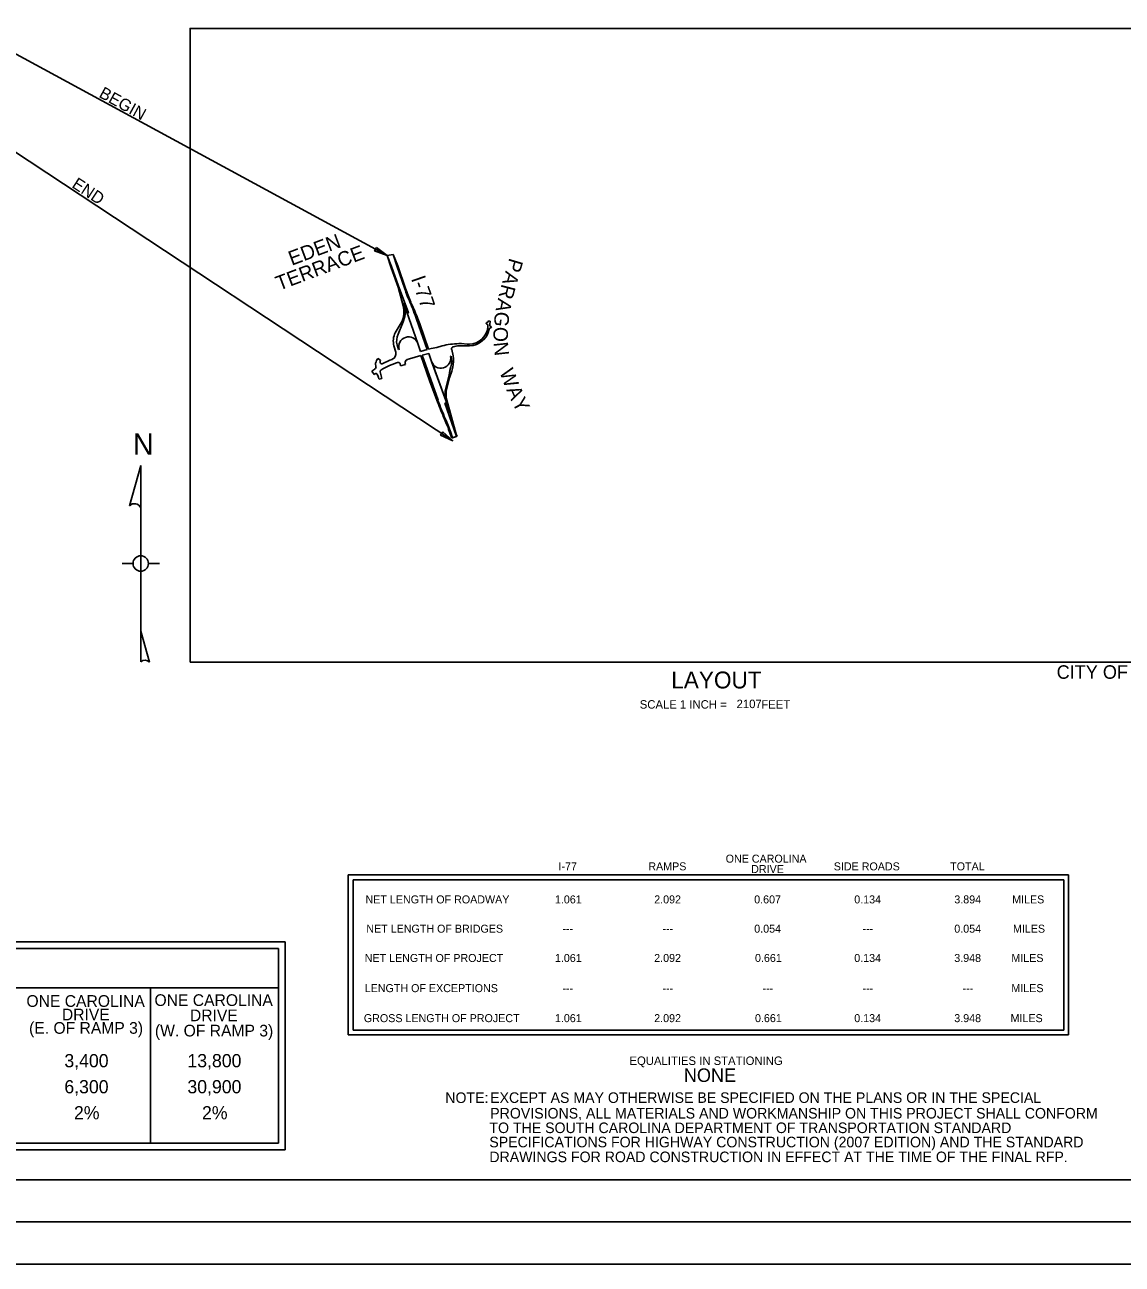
# Model space of a CAD drawing. Extents: x 1524103 to 2096450, y 1024229 to 1162569.
# Drawn here: x 2037540 to 2064966, y 1113991 to 1144974 of the extents above; entities that cross this region are included whole.
import ezdxf

# ---------------------------------------------------------------- set-up
doc = ezdxf.new("R2010")
doc.units = 0
for name, color, linetype in [('Default', 7, 'Continuous'), ('GN_TitleSheetMap', 7, 'Continuous'), ('RD_PD_EOP', 7, 'Continuous'), ('RD_SHT_Bndy', 7, 'Continuous'), ('RD_SHT_IplotShp', 7, 'Continuous'), ('RD_SHT_TX', 7, 'Continuous'), ('RD_TX_TitleSht', 7, 'Continuous')]:
    doc.layers.add(name, color=color, linetype=linetype)

msp = doc.modelspace()

# ---------------------------------------------------------------- linework, layer by layer
at = {"layer": 'GN_TitleSheetMap'}
msp.add_lwpolyline([(2041670, 1129041), (2068070, 1129041), (2068070, 1144881), (2041670, 1144881)], close=True, dxfattribs=at)
at = {"layer": 'RD_PD_EOP'}
for p, q in [((2046595, 1139210), (2046749, 1139230)), ((2046749, 1139230), (2046595, 1139210)), ((2046595, 1139210), (2046684, 1138923)), ((2046861, 1138951), (2046749, 1139230)), ((2046749, 1139230), (2046838, 1138948)), ((2046838, 1138948), (2046749, 1139230)), ((2046838, 1138948), (2047035, 1138376)), ((2047035, 1138376), (2046838, 1138948)), ((2047056, 1138383), (2046861, 1138951)), ((2046684, 1138923), (2046693, 1138897)), ((2046693, 1138897), (2046870, 1138411)), ((2046714, 1138904), (2046709, 1138917)), ((2046709, 1138917), (2046714, 1138904)), ((2046875, 1138461), (2046714, 1138904)), ((2046714, 1138904), (2046875, 1138461)), ((2046870, 1138411), (2046994, 1137948)), ((2047127, 1137771), (2046875, 1138461)), ((2046875, 1138461), (2047127, 1137771)), ((2047011, 1138018), (2047016, 1138020)), ((2047016, 1138020), (2047011, 1138018)), ((2047027, 1137957), (2047011, 1138018)), ((2047011, 1138018), (2047027, 1137957)), ((2047016, 1138020), (2047117, 1137767)), ((2047117, 1137767), (2047016, 1138020)), ((2047027, 1137957), (2047363, 1137008)), ((2047027, 1137957), (2047363, 1137009)), ((2047117, 1137767), (2047127, 1137771)), ((2047127, 1137771), (2047117, 1137767)), ((2046946, 1137523), (2046797, 1137275)), ((2046871, 1137239), (2046976, 1137508)), ((2046955, 1137541), (2046946, 1137523)), ((2046976, 1137508), (2046985, 1137526)), ((2047333, 1137611), (2047600, 1136856)), ((2047600, 1136856), (2047333, 1137611)), ((2047409, 1137497), (2047362, 1137622)), ((2047632, 1136865), (2047409, 1137497)), ((2049076, 1137532), (2049070, 1137501)), ((2049114, 1137447), (2049110, 1137408)), ((2049168, 1137561), (2049128, 1137573)), ((2049160, 1137480), (2049168, 1137561)), ((2049198, 1137403), (2049205, 1137426)), ((2046766, 1136949), (2046810, 1136789)), ((2046877, 1136856), (2046845, 1136970)), ((2046894, 1136861), (2046877, 1136856)), ((2047433, 1136810), (2047363, 1137008)), ((2047363, 1137008), (2047433, 1136810)), ((2047600, 1136856), (2047433, 1136810)), ((2047433, 1136810), (2047600, 1136856)), ((2047468, 1136713), (2047634, 1136759)), ((2047634, 1136759), (2047468, 1136713)), ((2047692, 1136882), (2047632, 1136865)), ((2047634, 1136759), (2047706, 1136554)), ((2047706, 1136554), (2047634, 1136759)), ((2047834, 1136908), (2047692, 1136882)), ((2047969, 1136945), (2047834, 1136908)), ((2048210, 1136857), (2048206, 1136856)), ((2048243, 1136696), (2048210, 1136857)), ((2048450, 1137004), (2048388, 1137003)), ((2048422, 1136948), (2048656, 1136951)), ((2048594, 1136993), (2048450, 1137004)), ((2048652, 1136993), (2048594, 1136993)), ((2046365, 1136635), (2046333, 1136584)), ((2046433, 1136594), (2046365, 1136635)), ((2046722, 1136615), (2046723, 1136611)), ((2046920, 1136498), (2046933, 1136450)), ((2046933, 1136450), (2047054, 1136483)), ((2047054, 1136483), (2047047, 1136507)), ((2047100, 1136608), (2047154, 1136627)), ((2047154, 1136627), (2047435, 1136704)), ((2047435, 1136704), (2047665, 1136054)), ((2047867, 1135586), (2047468, 1136713)), ((2047468, 1136713), (2047867, 1135586)), ((2048065, 1135580), (2047706, 1136554)), ((2048065, 1135580), (2047709, 1136548)), ((2048180, 1136683), (2048197, 1136687)), ((2046261, 1136350), (2046216, 1136318)), ((2046216, 1136318), (2046275, 1136234)), ((2046275, 1136234), (2046293, 1136246)), ((2046311, 1136444), (2046317, 1136419)), ((2046460, 1136130), (2046419, 1136300)), ((2048144, 1136212), (2048062, 1135893)), ((2048087, 1135886), (2048154, 1136147)), ((2048166, 1136330), (2048144, 1136212)), ((2048154, 1136147), (2048210, 1136319)), ((2048191, 1136427), (2048166, 1136330)), ((2048210, 1136319), (2048235, 1136416)), ((2046393, 1136125), (2046395, 1136114)), ((2046395, 1136114), (2046460, 1136130)), ((2047665, 1136054), (2047858, 1135545)), ((2048050, 1135516), (2048041, 1135513)), ((2048041, 1135513), (2048050, 1135516)), ((2048141, 1135282), (2048050, 1135516)), ((2048050, 1135516), (2048141, 1135282)), ((2048065, 1135580), (2048147, 1135284)), ((2048147, 1135284), (2048065, 1135580)), ((2048324, 1134743), (2048090, 1135587)), ((2048041, 1135513), (2048333, 1134686)), ((2048333, 1134686), (2048041, 1135513)), ((2048147, 1135284), (2048141, 1135282)), ((2048141, 1135282), (2048147, 1135284)), ((2048164, 1134775), (2048206, 1134656)), ((2048227, 1134652), (2048185, 1134783)), ((2048185, 1134783), (2048227, 1134652)), ((2048206, 1134656), (2048210, 1134647)), ((2048210, 1134647), (2048227, 1134652)), ((2048338, 1134688), (2048227, 1134652)), ((2048227, 1134652), (2048333, 1134686)), ((2048343, 1134689), (2048324, 1134743)), ((2048333, 1134686), (2048343, 1134689))]:
    msp.add_line(p, q, dxfattribs=at)
for points in [[(2046709, 1138917), (2046709, 1138917), (2046704, 1138929), (2046595, 1139210)], [(2046595, 1139210), (2046704, 1138929), (2046709, 1138917)], [(2047206, 1137998), (2047206, 1137998)]]:
    msp.add_lwpolyline(points, dxfattribs=at)
for centre, radius, start, end in [((2051713, 1139983), 4946, 198.9531, 203.2944), ((2051713, 1139983), 4946, 198.9531, 203.2944), ((2051713, 1139983), 4924, 198.9531, 203.2944), ((2041007, 1135373), 6710, 19.482, 23.2944), ((2041007, 1135373), 6710, 19.482, 23.2944), ((2041007, 1135373), 6732, 22.9513, 23.2944), ((2041064, 1135235), 6735, 20.7529, 24.2229), ((2041064, 1135235), 6735, 24.2229, 24.2235), ((2046433, 1137797), 581, 333.8563, 15.0109), ((2046433, 1137797), 615, 333.8563, 15.0109), ((2048648, 1137457), 464, 270.3929, 353.919), ((2049066, 1137453), 48.5, 353.919, 84.6269), ((2049080, 1137580), 48.5, 265.1461, 351.7715), ((2049193, 1137354), 48.5, 84.9978, 169.3164), ((2049208, 1137475), 48.5, 173.919, 266.9772), ((2047212, 1137071), 462, 153.8253, 195.3889), ((2047212, 1137071), 380, 153.8313, 195.3889), ((2047131, 1136926), 246, 19.482, 195.3889), ((2048648, 1137457), 506, 270.8238, 349.3164), ((2046672, 1136750), 144, 290.327, 15.3889), ((2047131, 1136926), 246, 19.482, 19.5594), ((2048399, 1135384), 1619, 90.3929, 105.3889), ((2048263, 1136868), 58.5, 106.1784, 191.3824), ((2048414, 1136349), 599, 91.819, 106.1784), ((2048445, 1135368), 1581, 90.8238, 91.819), ((2046489, 1136488), 183, 148.2706, 193.6417), ((2046457, 1136534), 38.5, 169.918, 297.8932), ((2046762, 1136480), 349, 160.9551, 169.918), ((2047439, 1134678), 1942, 107.393, 121.072), ((2047439, 1134678), 2061, 110.327, 117.8932), ((2046873, 1136485), 48.5, 15.3889, 107.393), ((2047128, 1136529), 83.5, 109.3689, 195.3889), ((2047938, 1136636), 246, 199.482, 10.9973), ((2047938, 1136636), 246, 199.482, 200.9312), ((2047626, 1136572), 583, 345.6281, 11.3824), ((2047626, 1136572), 629, 345.6281, 11.3824), ((2047439, 1134678), 2046, 123.8046, 125.1779), ((2046315, 1136215), 38.5, 30.7084, 125.1779), ((2046280, 1136410), 38.5, 303.8046, 13.6417), ((2046005, 1136031), 398, 13.6417, 30.7084), ((2046457, 1136309), 38.5, 121.072, 193.6417), ((2048650, 1135742), 607, 165.6281, 195.482), ((2048650, 1135742), 581, 165.6281, 195.482), ((2054192, 1137823), 6732, 199.7803, 203.7286), ((2054192, 1137823), 6710, 199.482, 203.7286), ((2054192, 1137823), 6710, 199.482, 203.7286), ((2043522, 1133133), 4924, 19.482, 23.7286), ((2043522, 1133133), 4946, 19.482, 23.7286), ((2043522, 1133133), 4946, 19.482, 23.7286)]:
    msp.add_arc(centre, radius, start, end, dxfattribs=at)
at = {"layer": 'RD_SHT_Bndy'}
for p, q in [((2063625, 1123722), (2045625, 1123722)), ((2045625, 1123722), (2045625, 1119722)), ((2063505, 1123602), (2045745, 1123602)), ((2045745, 1123602), (2045745, 1119840)), ((2063505, 1119840), (2063505, 1123602)), ((2063625, 1119722), (2063625, 1123722)), ((2020675, 1120902), (2043880, 1120902)), ((2040680, 1120902), (2040680, 1117015)), ((2043880, 1120902), (2043880, 1117015)), ((2045625, 1119722), (2063625, 1119722)), ((2045747, 1119842), (2063505, 1119842)), ((2019473, 1116103), (2090264, 1116103)), ((2016109, 1115047), (2090454, 1115047)), ((2016109, 1113991), (2090454, 1113991))]:
    msp.add_line(p, q, dxfattribs=at)
at = {"layer": 'RD_SHT_IplotShp'}
msp.add_lwpolyline([(2015439, 1161513), (2091301, 1161513), (2091301, 1115047), (2015439, 1115047)], close=True, dxfattribs=at)
at = {"layer": 'RD_SHT_TX'}
for points in [[(2044045, 1116850), (2020510, 1116850), (2020510, 1122046), (2044045, 1122046)], [(2043880, 1117015), (2020675, 1117015), (2020675, 1121881), (2043880, 1121881)]]:
    msp.add_lwpolyline(points, close=True, dxfattribs=at)
at = {"layer": 'RD_TX_TitleSht'}
for p, q in [((2040155, 1132950), (2040438, 1133961)), ((2040438, 1133961), (2040438, 1132896)), ((2040438, 1133961), (2040438, 1129053)), ((2039972, 1131507), (2040245, 1131507)), ((2040631, 1131507), (2040904, 1131507)), ((2040438, 1129813), (2040438, 1129053)), ((2040656, 1129041), (2040438, 1129813))]:
    msp.add_line(p, q, dxfattribs=at)
for points in [[(2028587, 1144286), (2037234, 1144286), (2046595, 1139210)], [(2028587, 1141836), (2037234, 1141836), (2048234, 1134577)]]:
    msp.add_lwpolyline(points, dxfattribs=at)
for points in [[(2046329, 1139410), (2046595, 1139210), (2046282, 1139323)], [(2047986, 1134800), (2048234, 1134577), (2047931, 1134718)]]:
    msp.add_lwpolyline(points, close=True, dxfattribs=at)
msp.add_circle((2040438, 1131507), 193, dxfattribs=at)
for centre, radius, start, end in [((2040279, 1132831), 172, 22.3707, 136.1387), ((2040541, 1128933), 158, 43.3397, 130.5607)]:
    msp.add_arc(centre, radius, start, end, dxfattribs=at)

# ---------------------------------------------------------------- texts
at = {"layer": 'Default'}
msp.add_text('2107', height=211.2, dxfattribs=at).set_placement((2055329, 1127892))
at = {"layer": 'RD_SHT_TX'}
for s, height, p in [('LAYOUT', 422.4, (2053695, 1128384)), ('SCALE 1 INCH =           FEET', 211.2, (2052909, 1127879)), ('ONE CAROLINA', 200, (2055056, 1124029)), ('I-77', 200, (2050878, 1123836)), ('RAMPS', 200, (2053123, 1123836)), ('DRIVE', 200, (2055693, 1123769)), ('SIDE ROADS', 200, (2057758, 1123836)), ('TOTAL', 200, (2060667, 1123836)), ('NET LENGTH OF ROADWAY', 200, (2046055, 1123010)), ('1.061', 200, (2050789, 1123010)), ('2.092', 200, (2053270, 1123010)), ('0.607', 200, (2055769, 1123010)), ('0.134', 200, (2058270, 1123010)), ('3.894', 200, (2060770, 1123010)), ('MILES', 200, (2062216, 1123010)), ('NET LENGTH OF BRIDGES', 200, (2046075, 1122278)), ('---', 200, (2050977, 1122278)), ('---', 200, (2053477, 1122278)), ('0.054', 200, (2055770, 1122278)), ('---', 200, (2058477, 1122278)), ('0.054', 200, (2060770, 1122278)), ('MILES', 200, (2062236, 1122278)), ('NET LENGTH OF PROJECT', 200, (2046035, 1121546)), ('1.061', 200, (2050789, 1121546)), ('2.092', 200, (2053270, 1121546)), ('0.661', 200, (2055789, 1121546)), ('0.134', 200, (2058270, 1121546)), ('3.948', 200, (2060769, 1121546)), ('MILES', 200, (2062196, 1121546)), ('LENGTH OF EXCEPTIONS', 200, (2046035, 1120792)), ('MILES', 200, (2062196, 1120792)), ('ONE CAROLINA', 292.72, (2037581, 1120424)), ('ONE CAROLINA', 292.72, (2040781, 1120446)), ('---', 200, (2050977, 1120792)), ('---', 200, (2053477, 1120792)), ('---', 200, (2055977, 1120792)), ('---', 200, (2058477, 1120792)), ('---', 200, (2060977, 1120792)), ('DRIVE', 292.7, (2038467, 1120087)), ('DRIVE', 292.7, (2041667, 1120065)), ('(E. OF RAMP 3)', 292.72, (2037647, 1119751)), ('GROSS LENGTH OF PROJECT', 200, (2046013, 1120042)), ('1.061', 200, (2050789, 1120042)), ('2.092', 200, (2053270, 1120042)), ('0.661', 200, (2055789, 1120042)), ('0.134', 200, (2058270, 1120042)), ('3.948', 200, (2060769, 1120042)), ('MILES', 200, (2062176, 1120042)), ('(W. OF RAMP 3)', 292.72, (2040792, 1119684)), ('EQUALITIES IN STATIONING', 211.2, (2052652, 1118972)), ('NOTE:', 264, (2048049, 1118021)), ('EXCEPT AS MAY OTHERWISE BE SPECIFIED ON THE PLANS OR IN THE SPECIAL ', 264.01, (2049170, 1118023)), ('PROVISIONS, ALL MATERIALS AND WORKMANSHIP ON THIS PROJECT SHALL CONFORM ', 264.01, (2049172, 1117633)), ('TO THE SOUTH CAROLINA DEPARTMENT OF TRANSPORTATION STANDARD ', 264.01, (2049152, 1117269)), ('SPECIFICATIONS FOR HIGHWAY CONSTRUCTION (2007 EDITION) AND THE STANDARD', 264.01, (2049150, 1116913)), ('DRAWINGS FOR ROAD CONSTRUCTION IN EFFECT AT THE TIME OF THE FINAL RFP.', 264.01, (2049150, 1116542))]:
    msp.add_text(s, height=height, dxfattribs=at).set_placement(p)
at = {"layer": 'RD_TX_TitleSht'}
for s, height, rotation, p in [('BEGIN', 300, 331.1816, (2039371, 1143177)), ('END', 300, 326.579, (2038695, 1140925)), ('EDEN', 362.4, 20.5838, (2044211, 1138948)), ('TERRACE', 362.4, 20.5838, (2043893, 1138324)), ('P', 362, 253.5498, (2049654, 1139161)), ('I-77', 362.4, 289.2317, (2047189, 1138629)), ('A', 362, 254.0152, (2049557, 1138835)), ('R', 362, 255.3563, (2049463, 1138508)), ('A', 362, 258.3308, (2049370, 1138152)), ('G', 362, 263.2968, (2049300, 1137819)), ('O', 362, 268.9977, (2049256, 1137425)), ('N', 362, 276.2937, (2049252, 1137028)), ('W', 362, 290.5461, (2049397, 1136301)), ('A', 362, 294.0439, (2049569, 1135852)), ('Y', 362, 297.5342, (2049707, 1135541))]:
    msp.add_text(s, height=height, rotation=rotation, dxfattribs=at).set_placement(p)
for s, height, p in [('N', 535, (2040242, 1134224)), ('CITY OF ROCK HILL', 337.92, (2063328, 1128625)), ('3,400', 330, (2038529, 1118914)), ('13,800', 330, (2041604, 1118914)), ('NONE', 337.9, (2054011, 1118547)), ('6,300', 330, (2038529, 1118263)), ('30,900', 330, (2041604, 1118263)), ('2%', 330, (2038769, 1117612)), ('2%', 330, (2041969, 1117612))]:
    msp.add_text(s, height=height, dxfattribs=at).set_placement(p)

doc.saveas('drawing.dxf')
